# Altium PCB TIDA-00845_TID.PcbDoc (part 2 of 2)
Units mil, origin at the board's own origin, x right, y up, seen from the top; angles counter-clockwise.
Board outline 5936.8 x 4260 mil, 4 copper layers (Top Layer, Layer 2, Layer 3, Bottom Layer), stack 61.2 mil thick; 144 components, 62 nets, 439 pads, 261 vias.
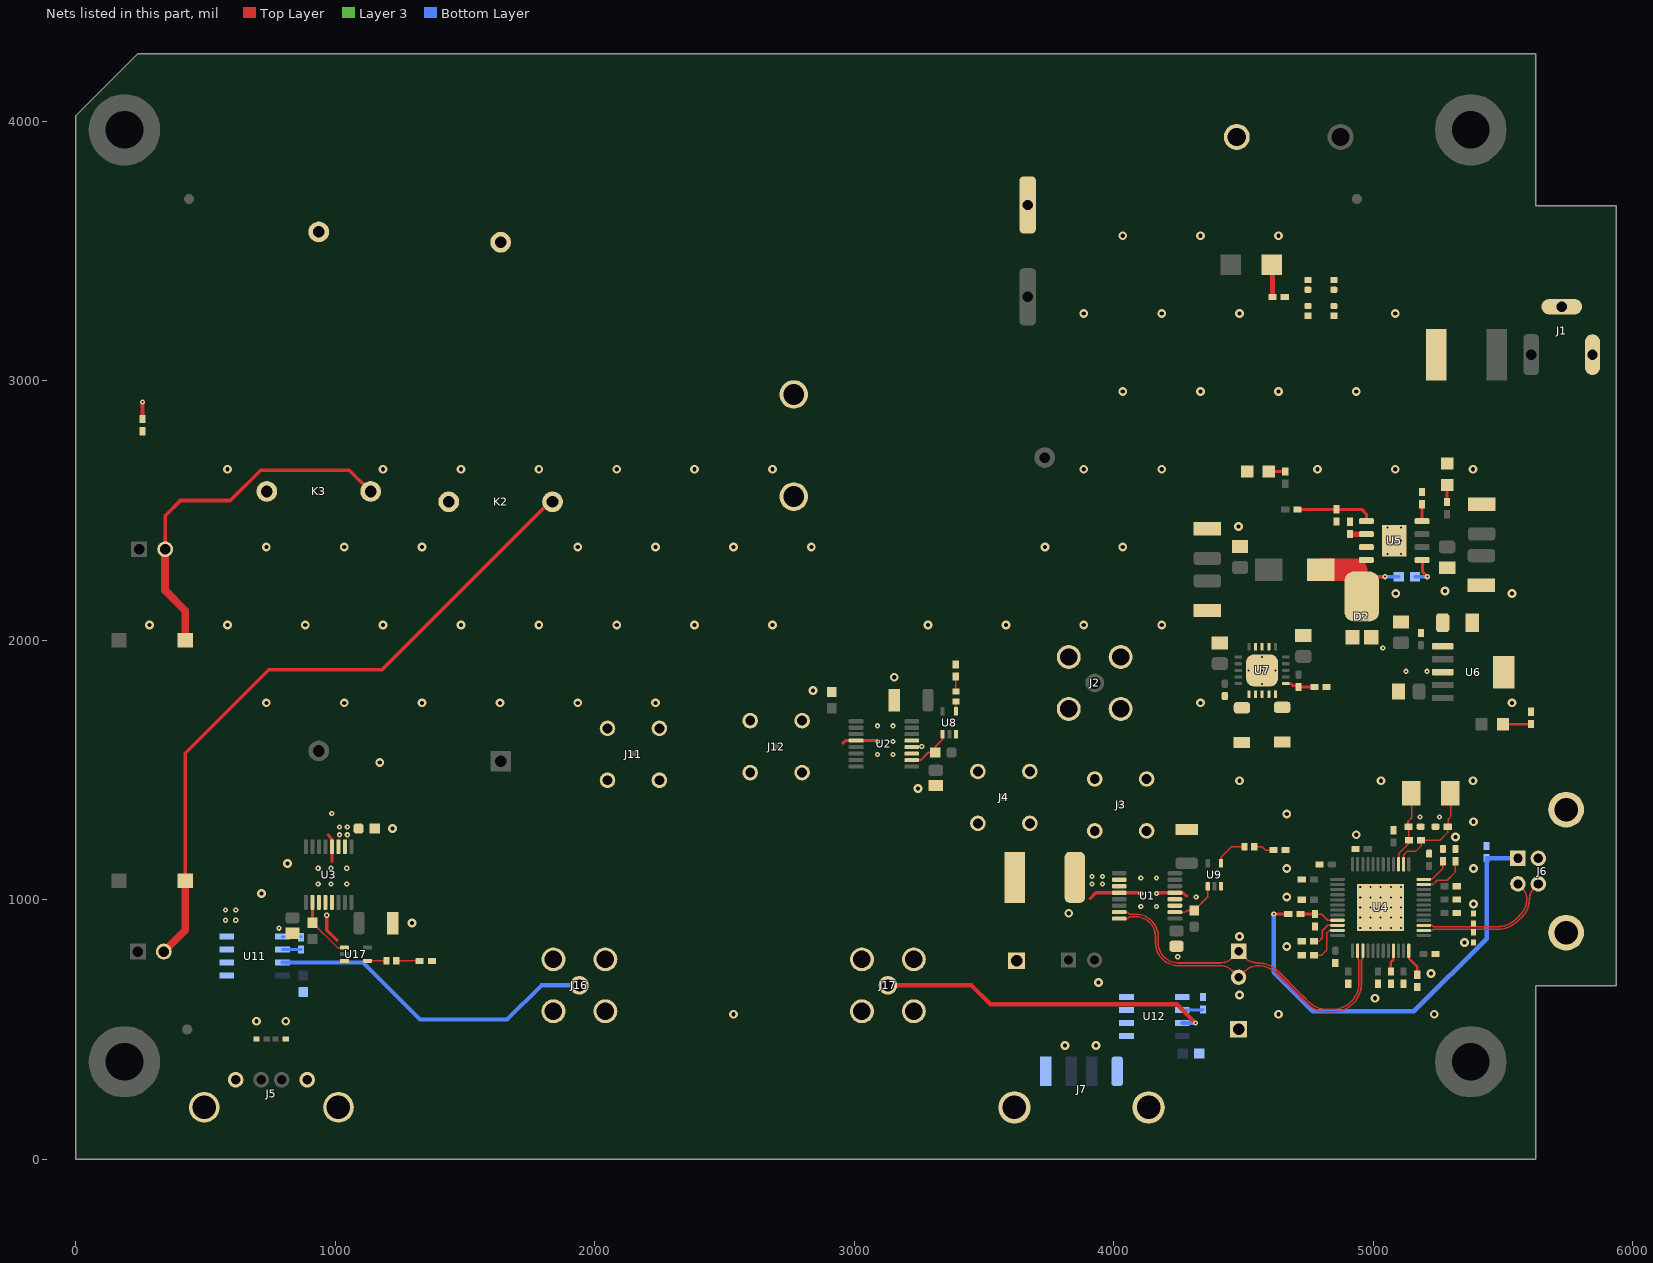
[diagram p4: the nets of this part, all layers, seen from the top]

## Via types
v1: diameter 19.68, hole 7.87, Top Layer to Bottom Layer, tented both sides, 170 vias
v2: diameter 34, hole 16, Top Layer to Bottom Layer, tented both sides, 91 vias

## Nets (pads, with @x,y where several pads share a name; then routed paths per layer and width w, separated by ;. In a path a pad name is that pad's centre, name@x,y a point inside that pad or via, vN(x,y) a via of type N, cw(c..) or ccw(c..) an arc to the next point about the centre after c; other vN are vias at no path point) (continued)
DP2_SYS_N: J8.2 U1.8 U4.15 | length 1344.2
  Top Layer w6.24: U1.8@4021.11,926.74 4053.03,926.74 4060.41,934.12 4083.95,934.12 cw(c4083.95,856.85) 4161.22,856.85 4161.18,833.32 ccw(c4248.69,833.32) 4248.69,745.81 4410.96,745.81 cw(c4410.96,684.19) 4454.53,727.76 J8.2@4481.36,700.93 4505.18,724.74 cw(c4556.03,673.89) 4556.03,745.81 cw(c4556.03,645.81) 4626.74,716.52 4709.96,633.3 4726.6,616.65 4743.25,600.01 ccw(c4821.2,677.96) 4821.2,567.72 4844.73,567.72 ccw(c4844.73,677.96) 4954.97,677.96 4954.97,767.83 4959.7,772.55 U4.15@4959.7,803.55 ccw(c4962.36,800.89) U4.15@4958.59,800.89
DP2_SYS_P: J8.1 U1.7 U4.14 | length 1328.1
  Top Layer w6.24: U1.7@4021.11,951.74 4053.03,951.74 4060.41,944.36 4083.95,944.36 cw(c4083.95,856.85) 4171.46,856.85 ; 4171.42,856.85 4171.42,833.32 ccw(c4248.69,833.32) 4248.69,756.05 4410.96,756.05 ccw(c4410.96,817.66) 4454.53,774.09 J8.1@4481.36,800.93 4505.18,777.11 ccw(c4556.03,827.96) 4556.03,756.05 cw(c4556.03,645.81) 4633.98,723.76 4717.2,640.54 4733.84,623.89 4750.49,607.25 ccw(c4821.2,677.96) 4821.2,577.96 4844.73,577.96 ccw(c4844.73,677.96) 4944.73,677.96 4944.73,767.83 4940.01,772.55 U4.14@4940.01,803.55 cw(c4937.35,800.89) U4.14@4941.11,800.89
FLT_U1: R26.1 U1.10 U9.1 | length 191.4
  Top Layer w6.24: U1.10@4235.68,951.74 4274.54,951.74 4281.29,958.5 R26.1@4309.8,958.5 4362.21,1010.91 U9.1@4362.21,1051.25
FLT_U2: R22.1 U2.10 U8.1 | length 185
  Top Layer w6: R22.1@3311.9,1567.05 3311.9,1589.46 3340.84,1618.4 U8.1@3340.84,1637.69
  Top Layer w8: U2.10@3221.68,1537.61 3255.84,1537.61 3285.28,1567.05 R22.1@3311.9,1567.05
FLT_U3: R23.2 U3.10 U17.1 | length 241.1
  Top Layer w6: R23.2@912.8,911.5 1008.7,815.59 U17.1@1035.84,815.59
  Top Layer w12: U3.10@912.31,989.64 912.31,911.98 R23.2@912.8,911.5
GND: C1.2 C3.2 C4.1 C5.1 C6.1 C7.2 C8.2 C9.2 C10.1 C11.2 C12.1 C13.2 C14.2 C15.1 C16.1 C17.2 C18.1 C19.1 C20.1 C21.1 C22.2 C23.1 C24.1 C25.1 C26.1 C27.1 C28.2 C29.2 C30.1 C31.1 C32.1 C33.1 C34.1 C35.1 C36.2 C37.2 C38.2 C39.2 C40.2 C41.2 C42.2 C43.2 C47.2 C48.2 C49.2 C50.2 C51.2 D1.2 D2.1 D2.2 D3.2 D10.2 D12.2 D13.2 D14.2 J1.2 J1.3 J2.2 J2.3 J2.4 J2.5 J3.2 J3.3 J3.4 J3.5 J4.2 J4.3 J4.4 J4.5 J5.4 J5.5 J5.6 J6.4 J6.5 J6.6 J7.4 J7.5 J7.6 J11.2 J11.3 J11.4 J11.5 J12.2 J12.3 J12.4 J12.5 J15.1 J16.2 J16.3 J16.4 J16.5 J17.2 J17.3 J17.4 J17.5 J18.1 K2.4 K3.4 R5.2 R6.2 R7.1 R15.1 R16.1 R17.2 R18.2 R19.1 R20.1 R21.1 R25.1 R27.2 R28.2 R31.2 U1.4 U1.11 U1.12 U1.13 U2.4 U2.11 U2.12 U2.13 U3.4 U3.11 U3.12 U3.13 U4.49 U5.7 U5.9 U6.3 U6.6 U7.2 U7.3 U7.4 U7.12 U7.13 U7.14 U7.21 U8.3 U9.3 U11.5 U12.5 U13.2 U14.2 U15.2 U16.2 U17.3 | length 2016.8
  Top Layer w10: 985.78,1235.66 U3.4@987.31,1204.21
  Top Layer w12: v1(967.63,940) 967.63,882.46 1007.39,842.69 ; 973.32,1248.82 984.87,1235.39 ; 987.31,1147.77 U3.4@987.31,1204.21 ; 2956.38,1602.65 2966.34,1612.61 U2.4@3007.11,1612.61 3087.62,1612.61 v1(3090.23,1610) ; 3909.03,1004.58 3931.2,1026.74 U1.4@4021.11,1026.74 4100.01,1026.74 v1@4101.43,1025.33 ; v1(4164.23,1024.13) 4166.84,1026.74 U1.13@4235.68,1026.74 4265.8,1026.74 4278.41,1014.13 4282.23,1014.13
  Layer 3 w18: v1(4949.85,891.15) v1(4949.85,930.52) v1(4949.85,969.89) v1(4949.85,1009.26) v1(4949.85,1048.63) v1(4989.22,1048.63) v1(5028.59,1048.63) v1(5067.96,1048.63) v1(5107.33,1048.63) v1(5107.33,1009.26) v1(5107.33,969.89) v1(5107.33,930.52) v1(5107.33,891.15) v1(5067.96,891.15) v1(5028.59,891.15) v1(4989.22,891.15) v1(4949.85,891.15)
  Bottom Layer w10: U11.5@796.92,857.89 C48.2@868.92,857.89
  Bottom Layer w18: v1(4949.85,891.15) v1(4949.85,930.52) v1(4949.85,969.89) v1(4949.85,1009.26) v1(4949.85,1048.63) v1(4989.22,1048.63) v1(5028.59,1048.63) v1(5067.96,1048.63) v1(5107.33,1048.63) v1(5107.33,1009.26) v1(5107.33,969.89) v1(5107.33,930.52) v1(5107.33,891.15) v1(5067.96,891.15) v1(5028.59,891.15) v1(4989.22,891.15) v1(4949.85,891.15)
  other v1: 4246.8,780 782.99,890 4989.22,930.52 5028.59,930.52 5067.96,930.52 4989.22,969.89 5028.59,969.89 5067.96,969.89 4104.23,974.13 4164.23,974.13 4989.22,1009.26 5028.59,1009.26 5067.96,1009.26 4317.8,1010 4104.23,1024.13 934.7,1061.09 984.7,1061.09 1044.7,1061.09 4104.23,1084.13 4164.23,1084.13 934.7,1121.09 984.7,1121.09 1044.7,1121.09 5179.89,1318.96 5255.7,1318.87 987.04,1332.23 3090.23,1560 3150.23,1560 3260.23,1590 3150.23,1610 3090.23,1670 3150.23,1670 4571.96,1831.22 5126.8,1880 5206.8,1880 4519.79,1883.39 4571.96,1883.39 4624.12,1883.39 4571.96,1935.55 5036.8,1970 5055.2,2332.31 5106.38,2332.31 5055.2,2383.49 5106.38,2383.49 5055.2,2434.67 5106.38,2434.67
  other v2: 3812.54,438.59 3931.6,438.1 697.11,531.49 809.48,531.49 2534.8,558.5 4634.8,558.5 5234.8,558.5 5006.8,620 4484.8,633.3 3941.34,680.4 5222.96,716.16 4666.8,820 5351.58,835.24 4484.8,858.5 1296.25,910.36 3826.8,947.81 5386.8,983 4666.8,1010 715.69,1024.13 4666.8,1120 5386.8,1120 815.8,1139.84 5317.4,1240.96 4934.8,1250 1221.56,1273.76 5386.8,1300 4666.8,1330 3246.29,1428.36 4484.8,1458.5 5030.11,1458.5 5384.8,1458.5 1171.86,1528.07 734.8,1758.5 1034.8,1758.5 1334.8,1758.5 1634.8,1758.5 1934.8,1758.5 2234.8,1758.5 4334.8,1758.5 5534.8,1758.5 2841.52,1806.12 3154.07,1857.2 284.8,2058.5 584.8,2058.5 884.8,2058.5 1184.8,2058.5 1484.8,2058.5 1784.8,2058.5 2084.8,2058.5 2384.8,2058.5 2684.8,2058.5 3284.8,2058.5 3584.8,2058.5 3884.8,2058.5 4184.8,2058.5 5086.8,2180 5534.8,2180 5276.8,2190 734.8,2358.5 1034.8,2358.5 1334.8,2358.5 1934.8,2358.5 2234.8,2358.5 2534.8,2358.5 2834.8,2358.5 3734.8,2358.5 4034.8,2358.5 4480.42,2438.54 584.8,2658.5 1184.8,2658.5 1484.8,2658.5 1784.8,2658.5 2084.8,2658.5 2384.8,2658.5 2684.8,2658.5 3884.8,2658.5 4184.8,2658.5 4784.8,2658.5 5084.8,2658.5 5384.8,2658.5 4034.8,2958.5 4334.8,2958.5 4634.8,2958.5 4934.8,2958.5 3884.8,3258.5 4184.8,3258.5 4484.8,3258.5 5084.8,3258.27 4034.8,3558.5 4334.8,3558.5 4634.8,3558.5
NetC1_1: C1.1 K2.1 K3.1 R4.2 R7.2 S1.1 | length 65.4
  Top Layer w15: R7.2@257.6,2852.36 v1(257.6,2917.74)
NetC2_1: C2.1 D2.3 L1.1 U5.8 | length 230.8
  Top Layer w12: D2.3@5004.8,2244.49 v1(5045.8,2244.49)
  Top Layer w86.61: L1.1@4798.19,2271 4933.05,2271 4934.8,2269.25
  Bottom Layer w12: v1(5045.8,2244.49) C2.1@5098.3,2244.49
NetC2_2: C2.2 U5.1 | length 119.3
  Top Layer w12: U5.1@5188.07,2308.49 5189.78,2306.78 5189.78,2262.92 v1(5208.21,2244.49)
  Bottom Layer w12: C2.2@5161.29,2244.49 v1(5208.21,2244.49)
NetC10_2: C10.2 U5.6 | length 63.9
  Top Layer w12: C10.2@4909.79,2408.87 C10.2@4910.17,2408.49
  Top Layer w22: C10.2@4910.17,2408.49 U5.6@4973.5,2408.49
NetC12_2: C12.2 U4.11 | length 167.6
  Top Layer w6: C12.2@4771.79,786.03 4800.47,786.03 4821.6,807.17 4821.6,871.5 4831.42,881.31 U4.11@4862.26,881.31
NetC13_1: C13.1 R8.1 U4.39 Y1.1 | length 297.5
  Top Layer w6: U4.39@5097.49,1136.23 5097.49,1176.55 5137.19,1216.25 R8.1@5137.19,1229.21 5137.19,1279.33 C13.1@5135.37,1281.15 5133.99,1282.53 5133.99,1301.65 5148.41,1316.07 Y1.1@5148.41,1410
NetC14_1: C14.1 R8.2 U4.38 Y1.2 | length 411.2
  Top Layer w6: U4.38@5117.18,1136.23 5117.18,1172.11 5132.26,1187.19 5164.55,1187.19 5184.43,1207.07 R8.2@5184.43,1229.21 5256.92,1229.21 5288.36,1260.65 5286.98,1262.03 C14.1@5286.98,1281.15 5289.28,1283.45 5289.28,1310.22 5298.02,1318.96 Y1.2@5298.02,1410
NetC15_2: C15.2 R13.1 U6.1
NetC16_2: C16.2 R14.1 U7.11
NetC18_2: C18.2 U7.15
NetC48_1: C48.1 U11.6 | length 72.1
  Bottom Layer w10: U11.6@796.96,807.85 C48.1@868.96,807.85
NetC50_1: C50.1 U12.6 | length 80.3
  Bottom Layer w12: U12.6@4264.08,575 4341.09,575 C50.1@4343.39,577.3
NetC51_1: C51.1 J6.1 R24.1 | length 1709.6
  Top Layer w12: v1(4616.8,944.3) R24.1@4672.55,944.3
  Bottom Layer w18: v1(4616.8,944.3) 4616.8,720 4766.8,570 5156.8,570 5436.8,850 C51.1@5436.8,1160.13 5437.82,1159.11 J6.1@5557.64,1159.11
NetD1_1: D1.1 R1.1 | length 65
  Top Layer w12: R1.1@5284.8,2532.62 D1.1@5284.8,2597.66
NetD3_1: D3.1 R3.2 | length 64
  Top Layer w12: D3.1@4597.17,2649.64 R3.2@4661.17,2649.64
NetD7_2: D7.2 R15.2 | length 108.2
  Top Layer w10: D7.2@5499.79,1675.86 5606.38,1675.86 R15.2@5607.51,1677
NetD8_1: D8.1 U8.4 | length 35.2
  Top Layer w6: U8.4@3392.02,1726.27 D8.1@3392.02,1761.46
NetD8_2: D8.2 R27.1 | length 60.8
  Top Layer w6: R27.1@3391.45,1859.37 3392.02,1858.8 D8.2@3392.02,1798.86
NetD9_1: D9.1 U9.4 | length 131.5
  Top Layer w6: U9.4@4413.39,1139.84 4413.39,1163.59 4454.01,1204.21 D9.1@4504.31,1204.21
NetD9_2: D9.2 R28.1 | length 78.9
  Top Layer w6: D9.2@4541.71,1204.21 4570.59,1204.21 4583.8,1191 R28.1@4615.17,1191
NetD10_1: D10.1 D12.1 D13.1 D14.1 R30.2
NetD11_2: D11.2 R30.1 | length 125.8
  Top Layer w20: D11.2@4608.35,3447.15 4611.96,3443.54 R30.1@4611.96,3322.83
NetD15_1: D15.1 U17.4 | length 73.7
  Top Layer w6: U17.4@1124.42,764.41 D15.1@1198.1,764.41
NetD15_2: D15.2 R31.1 | length 90
  Top Layer w6: D15.2@1235.5,764.41 R31.1@1325.49,764.41
NetJ13_2: J13.2 K2.3 S2.1 | length 2619.3
  Top Layer w14: S2.1@422.75,1073 422.75,1564.75 743.8,1885.8 1180.49,1885.8 K2.3@1837.8,2543.11
  Top Layer w30: J13.2@340,800 422.75,882.75 S2.1@422.75,1073
NetJ14_2: J14.2 K3.3 S3.1 | length 1420.2
  Top Layer w14: J14.2@344.8,2350 344.8,2479.01 403.87,2538.08 596.07,2538.08 713.19,2655.2 1054.6,2655.2 K3.3@1143.8,2566
  Top Layer w30: J14.2@344.8,2350 344.8,2191.4 422.75,2113.44 S3.1@422.75,2000
NetJ16_1: J16.1 U11.7 | length 1289.7
  Bottom Layer w16: U11.7@796.92,757.89 1107.12,757.89 1326.8,538.21 1662.9,538.21 1794.69,670 J16.1@1941.05,670
NetJ17_1: J17.1 U12.7 | length 1296.9
  Top Layer w16: J17.1@3129.74,670 3452.58,670 3525.55,597.03 4243.3,597.03 v1(4315.33,525)
  Bottom Layer w16: U12.7@4264.08,525 v1(4315.33,525)
NetR2_2: R2.2 R5.1 U5.5 | length 300.3
  Top Layer w12: R2.2@4708.42,2504.11 R5.1@4858.79,2504.11 4955.69,2504.11 4973.5,2486.29 U5.5@4973.5,2458.49
NetR6_1: R6.1 U5.4 | length 64.9
  Top Layer w12: U5.4@5188.07,2458.49 R6.1@5188.07,2523.38
NetR12_1: R12.1 R16.2 U7.16 | length 114.8
  Top Layer w10.5: U7.16@4663.49,1832.2 4683.21,1832.2 4691.46,1823.96 4707.76,1823.96 R12.1@4711.96,1819.76 R16.2@4773.12,1819.76
NetR17_1: R17.1 U4.24 | length 106.3
  Top Layer w10: U4.24@5136.86,803.55 5136.86,773.93 5169.79,741 R17.1@5169.8,710.94
NetR18_1: R18.1 U4.10 | length 131.4
  Top Layer w6: R18.1@4771.79,839.89 4790.56,839.89 4803.91,853.24 4803.91,879.92 4824.98,901 U4.10@4862.26,901
NetR19_2: R19.2 U4.21 | length 84.1
  Top Layer w10: R19.2@5067.96,723.51 5067.96,759.55 5077.81,769.39 U4.21@5077.81,803.55
NetR20_2: R20.2 U4.35 | length 183.3
  Top Layer w6: U4.35@5194.93,1058.48 5229.84,1058.48 5246.26,1074.9 5284.77,1074.9 5316.59,1106.73 R20.2@5316.59,1148.33
NetR21_2: R21.2 U4.36 | length 118.4
  Top Layer w6: U4.36@5194.93,1078.16 5225.22,1078.16 5268.59,1121.54 R21.2@5268.59,1148.33
NetR24_2: R24.2 R25.2 U4.9 | length 152.2
  Top Layer w6: R25.2@4776.17,944.3 4801.32,944.3 4824.94,920.68 U4.9@4862.26,920.68
  Top Layer w12: R24.2@4719.79,944.3 R25.2@4776.17,944.3
UP_N: J6.2 U4.27 U15.1 | length 525.6
  Top Layer w6.24: U4.27@5194.93,901 5225.93,901 5230.66,896.27 ; 5230.66,896.29 5479.77,896.29 ccw(c5479.77,996.29) 5550.48,925.58 5566.5,941.59 ccw(c5505.2,1002.89) 5591.89,1002.89 ccw(c5535.06,1002.89) 5575.24,1043.07 J6.2@5557.64,1060.68
UP_P: J6.3 U4.26 U16.1 | length 541.7
  Top Layer w6.24: U4.26@5194.93,881.31 5225.93,881.31 5230.66,886.03 5479.77,886.05 ccw(c5479.77,996.29) 5557.72,918.34 5573.74,934.35 ccw(c5505.2,1002.89) 5602.13,1002.89 cw(c5658.95,1002.89) 5618.77,1043.07 J6.3@5636.38,1060.68
VBUS1_CON_SENSE_IN: C28.1 U3.2 U3.3 U11.3 U11.4
  other v1: 577.03,920.65 617.03,920.65 577.03,960.65 617.03,960.65 1016.8,1250 1046.8,1250 1016.8,1280 1046.8,1280
VBUS1_CON_SENSE_OUT: J5.1 U11.1 U11.2
VBUS2_CON_SENSE_IN: C36.1 U1.2 U1.3 U12.3 U12.4
  other v1: 3916.8,1060 3956.8,1060 3916.8,1090 3956.8,1090
VBUS2_CON_SENSE_OUT: J7.1 U12.1 U12.2
pads on no net: FID1.1 FID2.1 FID3.1 H1.1 H2.1 H3.1 H4.1 U1.1 U1.16 U2.1 U2.16 U3.1 U3.16 U4.2 U4.3 U4.4 U4.5 U4.6 U4.8 U4.16 U4.17 U4.19 U4.20 U4.22 U4.28 U4.29 U4.31 U4.32 U4.43 U4.44 U4.46 U4.47 U7.9 U7.17

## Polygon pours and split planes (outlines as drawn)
DP1_STB_VBUS on Top Layer "Top_Power" (solid, remove dead copper, pour order 312): 2994.8,1629.86 3033.8,1629.86 3035.8,1631.86 3035.8,1632.86 3035.8,1666.86 3031.8,1670.86 3028.8,1670.86 2967.8,1670.86 2945.8,1692.86 2945.8,1745.86 2881.8,1745.86 2881.8,1629.86
+3P3 on Top Layer "Top_Power" (solid, pour order 306): 3193.23,1519.99 3193.23,1500 3216.23,1477 3245.23,1477 3422.07,1477 3422.07,1585 3355.23,1585 3290.23,1520
+5V on Top Layer "Top_Power_1a" (solid, pour order 269): 3263.13,1747.42 3263.13,1686.22 3247.77,1670.86 3239.8,1670.86 3192.8,1670.86 3192.8,1629.86 3305.21,1629.86 3305.21,1737.69
+3P3 on Top Layer "Top_Power_1a" (solid, pour order 267): 5218.79,856.89 5214.79,852.89 5214.79,780 5174.79,780 5174.79,852.89 5171.79,855.89 5171.79,856.89
+3P3 on Top Layer "Top_Power_1a" (solid, pour order 268): 5141.59,1160.09 5145.59,1156.09 5226.8,1156.09 5226.8,1116.09 5145.59,1116.09 5142.59,1113.09 5141.59,1113.09
+3P3 on Top Layer "Top_Power_1a" (solid, pour order 271): 4920.51,1107.45 4911.59,1116.37 4824.47,1116.37 4824.47,1156.37 4911.59,1156.37 4914.59,1159.37 4920.51,1159.37
+1P1 on Top Layer "Top_Power_1a" (solid, pour order 270): 4839.79,856.89 4839.79,787.89 4881.79,787.89 4881.79,852.89 4885.79,856.89 4885.79,857.89 4884.79,856.89 4839.79,856.89
NetC2_1 on Top Layer "Top_Power_1b" (solid, pour order 282): 4843.47,2320 5001.8,2320 5001.8,2291 5021.8,2271 5021.8,2268 5021.8,2072 5020.8,2073 4879.8,2073 4843.47,2109.33
+5V on Top Layer "Top_Power" (solid, pour order 293): 4650.8,2314.86 4307.55,2314.86 4307.55,2228 4650.8,2228
+18V on Top Layer "Top18V" (solid, remove dead copper, pour order 285): 5158.8,2421 5237.8,2421 5253.8,2437 5297.39,2437 5475.11,2437 5499.75,2461.64 5499.83,3203.75 5579.71,3203.75 5637.16,3203.75 5684.58,3156.32 5684.58,2392.42 5590.16,2298 5505.8,2298 5487.8,2298 5357.8,2298 5322.8,2333 5236.77,2333 5224.77,2345 5219.8,2345 5158.8,2345
+5V on Top Layer "Top_Power" (solid, remove dead copper, pour order 294): 4525.96,1989.46 4494.96,1989.46 4439.96,1989.46 4440.07,1934.57 4377.96,1934.57 4377.97,1883.39 4413.29,1848.06 4413.96,1846.46 4413.96,1815.46 4414.96,1814.46 4495.09,1814.46 4494.96,1837.46 4459.96,1837.46 4439.96,1857.46 4439.96,1862.46 4440.96,1863.46 4440.96,1877.46 4494.96,1877.46 4494.96,1944.46 4509.96,1959.46 4510.96,1960.46 4525.96,1960.46
NetC16_2 on Top Layer "Top_Power" (solid, remove dead copper, pour order 295): 4526.58,1806.46 4415.96,1806.46 4415.96,1764.46 4462.96,1717.46 4464.67,1717.46 4526.58,1717.46 4526.58,1806.46
NetC18_2 on Top Layer "Top_Power" (solid, pour order 296): 4616.96,1806.46 4616.96,1719.46 4680.96,1719.46 4680.96,1764.46 4638.96,1806.46 4632.96,1806.46 4616.96,1806.46
+1P1 on Top Layer "Top_Power" (solid, remove dead copper, pour order 297): 4648.96,1877.46 4678.96,1877.46 4678.96,1851.46 4777.96,1851.46 4777.96,1895.46 4788.51,1906.01 4896.8,1906.71 4896.8,1961.46 4698.96,1961.46 4678.96,1941.46 4674.96,1941.46 4648.96,1941.46 4647.96,1940.46 4647.96,1877.46
+3P3 on Top Layer "Top_Power" (solid, pour order 298): 5308.8,1838 5150.8,1838 5150.8,1690 5308.8,1690
NetC15_2 on Top Layer "Top_Power" (solid, pour order 299): 5293.8,2104 5293.8,2022 5308.8,2007 5308.8,1996 5308.8,1959 5174.8,1959 5174.8,2055 5223.8,2104 5293.8,2104
+5V on Top Layer "Top_Power" (solid, pour order 300): 4416.8,1815 4333.8,1815 4333.8,1934.57 4416.8,1934.57
+5V on Top Layer "Top_Power" (solid, pour order 304): 4288.25,1160.49 4276.77,1137 4276.77,1100 4261.77,1085 4253.8,1085 4206.8,1085 4206.8,1044 4323.27,1044 4323.27,1153.92 4290.42,1161.52
+3P3 on Top Layer "Top_Power" (solid, pour order 308): 4213.8,934 4328.8,934 4328.8,858 4213.8,858
+3P3 on Top Layer "Top_Power" (solid, remove dead copper, pour order 318): 4364.09,892.55 4364.09,822 4282.1,822 4282.1,892.55
GND on Top Layer "Top_DGND" (solid, remove dead copper, pour order 332): 0,4260 5626.8,4260 5626.8,3673.5 5936.8,3673.5 5936.8,668.5 5626.8,668.5 5626.8,0 0,0
+5V on Top Layer "Top_Power1" (solid, pour order 292): 5222.8,1917 5074.8,1917 5074.8,1996 5195.8,1996 5195.8,1964 5222.8,1937 5222.8,1918
VBUS2_CON_SENSE_IN on Top Layer "Top_Power" (solid, remove dead copper, pour order 310): 4008.8,1044 4047.8,1044 4049.8,1046 4049.8,1047 4049.8,1081 4045.8,1085 4042.8,1085 3981.8,1085 3891.9,1174.9 3840.89,1174.9 3840.89,1087.57 3840.89,1056.29 3853.19,1044
VBUS1_CON_SENSE_IN on Top Layer "Top_Power" (solid, remove dead copper, pour order 314): 1003.8,1185 1003.8,1181 1009.8,1175 1010.8,1175 1038.8,1175 1040.8,1175 1045.8,1180 1045.8,1186 1045.8,1223 1045.8,1231.15 1070.19,1255.55 1084.7,1255.55 1084.7,1292.97 1003.8,1292.97
+5V on Top Layer "Top_Power" (solid, remove dead copper, pour order 301): 1004.8,1012 1004.8,1015 1007.8,1018 1009.8,1018 1040.8,1018 1044.8,1014 1044.8,965 1056.8,953 1065.8,953 1112.8,953 1112.8,867 1004.8,867 1004.8,1012
+5V on Top Layer "Top_5V" (solid, remove dead copper, pour order 302): 46.69,781.97 46.69,2331.74 74.93,2359.99 116.6,2360.02 116.86,785.55 81.73,750.41 78.25,750.41
+3P3 on Top Layer "Top_Power" (solid, remove dead copper, pour order 313): 892.33,1012.31 863.95,1012.15 815.8,964 815.8,909 862.8,909 864.58,910.78 864.58,951.26 877.32,964 879.8,964 892.8,964 892.33,964.46
+5V on Top Layer "Top_Power" (solid, pour order 305): 4434.95,2313.8 4434.95,2058.27 4534.96,2058.27 4534.96,2313.8
NetD10_1 on Top Layer "Top_D10" (solid, remove dead copper, pour order 278): 4860.97,3360 4695.66,3360 4658.49,3322.83 4701.14,3280.19 4860.97,3278.24
+1P1 on Top Layer "L1_1pt1" (solid, remove dead copper, pour order 65): 4617.14,1989.39 4673.33,1989.39 4704.19,1958.53 4704.19,1956.39 4704.19,1940 4648.19,1940 4617.14,1971.04 4617.14,1989.39
+5V on Top Layer "Top Layer-5Vg" (solid, remove dead copper, pour order 59): 100,1430 140,1430 160,1410 160,1360 140,1340 100,1340
GND on Layer 2 "L2_DGND" (solid, remove dead copper, pour order 330): 0,4260 5626.8,4260 5626.8,3673.5 5936.8,3673.5 5936.8,668.5 5626.8,668.5 5626.8,0 0,0
NetC1_1 on Layer 2 "L2_Cap_18V" (solid, remove dead copper, pour order 322): 0,4260 3791.03,4260 3791.03,3414.64 3217.64,2841.26 0,2841.26
NetC1_1 on Layer 2 "L2_Cap_18" (solid, remove dead copper, pour order 277): 3790.22,4260 3790.22,3518.74 3314.58,3518.74 3314.58,4260
VBUS1_CON_SENSE_OUT on Bottom Layer "Bot_5Vb" (solid, pour order 281): 553.87,620.5 553.87,770.65 609.84,770.65 638.83,741.67 638.83,620.5
VBUS1_CON_SENSE_IN on Bottom Layer "Bot_VBUS1_SYS" (solid, pour order 316): 553.87,976.72 553.87,795.3 608.65,795.3 638.83,825.47 638.83,976.72
VBUS1_CON_SENSE_OUT on Bottom Layer "Bot_5Va" (solid, pour order 283): 786.26,420 786.26,388.31 858.16,316.4 869.8,316.4 869.8,420
VBUS1_CON_SENSE_OUT on Bottom Layer "Bot_5Vaaa" (solid, pour order 280): 936.28,357.18 936.28,287.84 921.68,273.24 863.3,273.24 851.32,285.22 851.32,419.41 874.05,419.41
VBUS1_CON_SENSE_OUT on Bottom Layer "Bot_5Va" (solid, pour order 284): 580.81,684.4 608.93,684.4 915.35,377.97 796.68,377.97 554.28,620.36
VBUS2_CON_SENSE_IN on Bottom Layer "Bot_5V_1" (solid, remove dead copper, pour order 287): 3896.8,1100 3906.8,1110 3966.8,1110 4134.81,941.99 4134.81,617.4 4078.17,560.77 4021.36,560.77 4021.36,915.43 3896.8,1040
GND on Bottom Layer "Bot_DGND" (solid, remove dead copper, pour order 329): 0,4260 5626.8,4260 5626.8,3673.5 5936.8,3673.5 5936.8,668.5 5626.8,668.5 5626.8,0 0,0
+3P3 on Bottom Layer "Bot_3p3" (solid, remove dead copper, pour order 317): 5169.63,1770 5246.8,1770 5264.55,1752.25 5266.8,1750 5266.8,830 5126.8,690 4736.8,690 4736.8,800 4736.8,1100 5146.8,1510 5146.8,1620 5146.8,1747.17
VBUS2_CON_SENSE_OUT on Bottom Layer "Bot_5V" (solid, remove dead copper, pour order 303): 4079.83,537.43 4021.59,537.43 3991.89,507.73 3991.89,281.25 4079.84,281.25
GND on Bottom Layer "Bot_AGND_Priority" (solid, remove dead copper, pour order 291): 4989.22,930.52 4986.8,928.1 4986.8,850 4936.8,800 4936.8,650 5156.8,650 5231.8,725 5146.8,810 5146.8,860 5147.75,860.96 5147.75,960.05 5137.91,969.89 4989.22,969.89
DP1_STB_VBUS on Layer 3 "L3_STB" (solid, remove dead copper, pour order 286): 2961.8,2030.12 2881.8,2030.12 2881.8,1640 2891.8,1630 2951.8,1630 2961.8,1640 2961.8,2000
+3P3 on Layer 3 "L3_3p3_2" (solid, remove dead copper, pour order 288): 863.95,1012.15 815.8,964 815.8,790 1004.87,600.93 1495.13,600.93 1721.19,826.99 4227.97,826.99 4370.06,684.9 4793.17,684.9 4809.67,701.39 4809.67,704.3 4809.67,750 4795.29,764.38 4652.19,764.38 4516.8,764.71 3733.15,1548.35 3572.71,1548.35 3348.07,1548.35 3080.86,1281.15 1720.15,1281.15 1265.99,826.99 1254.83,826.99 946.8,826.99 882.33,891.45 882.33,995.89 868.22,1010 864.58,1010
+5V on Layer 3 "L3_5V" (solid, remove dead copper, pour order 290): 83.22,1353.68 83.22,1415.89 97.32,1430 1566.8,1430 1566.8,951.26 1066.8,951.26 1105.54,990 1106.8,990 1101.76,995.04 1101.76,1302.77 1064.53,1340 96.9,1340
+18V on Layer 3 "L3_18V" (solid, remove dead copper, pour order 320): 4690.28,3830 4699.97,3830 5573.04,2956.92 5936.8,2956.92 5936.8,3673.5 5626.8,3673.5 5626.8,4260 4690.28,4260
+1P1 on Layer 3 "L3_1p1" (solid, remove dead copper, pour order 307): 4825.42,1978.01 4865.42,1978.01 4885.42,1958.01 4885.42,1938.01 4885.42,1348.01 5196.8,1036.63 5196.8,990 5126.8,920 4986.8,920 4880.57,818.01 4815.42,818.01 4785.42,848.01 4765.42,868.01 4765.42,1958.01 4785.42,1978.01
+5V on Layer 3 "L3_5V" (solid, remove dead copper, pour order 311): 4446.75,2218.38 4526.84,2218.38 4536.8,2208.43 4536.8,2140 4566.8,2110 4586.8,2090 5106.8,2090 5206.8,1990 5206.8,1980 5206.8,1930 5196.8,1920 5186.8,1920 4716.8,1920 4656.8,1980 4526.8,1980 4466.8,1920 4456.8,1920 4466.8,1920 4406.8,1860 4406.8,1840 4406.8,1820 4396.8,1810 4336.8,1810 4326.8,1820 4326.8,1920 4436.8,2030 4436.8,2208.43
+5V on Layer 3 "L3_5V" (solid, remove dead copper, pour order 309): 4326.8,1920 4216.8,1920 4013.32,1716.53 4013.32,1293.47 4256.8,1050 4266.8,1040 4316.8,1040 4326.8,1050 4326.8,1550 4246.8,1550 4246.8,1820 4326.8,1820
+5V on Layer 3 "L3_5V_3" (solid, pour order 289): 4176.8,1278.38 3858.43,1278.38 3406.96,826.91 1048.96,826.91 996.8,879.07 996.8,947 1414.23,1364.43 2634.79,1870 4176.8,1870
NetC1_1 on Layer 3 "L3_18V_Cap" (solid, remove dead copper, pour order 272): 0,4260 3601.32,4260 3601.32,3224.33 3217.64,2840.65 0,2840.66
VBUS1_CON_SENSE_IN on Layer 3 "L3_5V" (solid, remove dead copper, pour order 315): 1066.8,1290 1050.64,1306.16 712.95,1306.15 553.73,1146.93 553.73,917.72 569.04,902.4 621.47,902.4 638.69,919.62 638.69,1102.02 762.53,1225.86 1052.65,1225.86 1066.8,1240
GND on Layer 3 "L3_DGND" (solid, remove dead copper, pour order 331): 0,4260 5626.8,4260 5626.8,3673.5 5936.8,3673.5 5936.8,668.5 5626.8,668.5 5626.8,0 0,0
+1P1 on Layer 3 "L3_1p1" (solid, remove dead copper, pour order 319): 4828.79,818.01 4936.8,710 4956.8,710 5006.8,710 5016.8,720 5016.8,750 5016.8,830 5016.8,870 5016.8,880 5016.8,890 4986.8,920 4964.63,942.16 4960.94,942.16 4961.41,942.63 4961.41,945.92 4957.33,950 4946.8,950 4826.8,830 4826.8,820 4828.79,818.01
NetC1_1 on Layer 3 "L3_+18V1" (solid, remove dead copper, pour order 276): 4691.69,4260 4691.69,3467.1 3305.92,3467.1 3305.92,4260
DP1_STB_VBUS on Layer 3 "L3_STB_a" (solid, remove dead copper, pour order 279): 3781.13,3541.1 3781.13,2689.01 2950.92,1858.8 2885.25,1858.8 2885.25,2674.78 2890.81,2680.34 3291.06,3080.92 3291.06,3089.1 3743.06,3541.1

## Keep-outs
Keep-Out Layer:
  lines w10: -5,4027.07 -5,-5 5631.8,-5 5631.8,663.5 5941.8,663.5 5941.8,3678.5 5631.8,3678.5 5631.8,4265 232.93,4265 -5,4027.07 ; -5,4027.07 -5,4027.07
  text ".Layer_Name" at 203.8,-1315.99 h60

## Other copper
Top Layer:
  pour cut-out: 4552.13,2416.67 4843.47,2416.67 4843.47,2125.33 4552.13,2125.33
  pour cut-out: 4090.74,1544.19 4090.74,2855 5429.75,2855 5500.38,2855 5500.38,2799.18 4164.23,2799.18 4161.88,2796.84 4161.88,1544.19
  pour cut-out: 5067.96,1489.75 5363.64,1489.75 5363.64,1336.07 5067.96,1336.08
  text ".Layer_Name" at 203.8,-1315.99 h60
Layer 2:
  pour cut-out: 4550.46,2416.67 4841.8,2416.67 4841.8,2125.33 4550.46,2125.33
  pour cut-out: 4090.74,1543.11 4090.74,2855 5429.75,2855 5500.38,2855 5500.38,2799.18 4164.23,2799.18 4161.88,2796.84 4161.88,1543.11
Layer 3:
  pour cut-out: 4550.46,2416.67 4841.8,2416.67 4841.8,2125.33 4550.46,2125.33
  pour cut-out: 4092.5,1894.41 cw(c4092.5,1896.16) 4090.74,1896.16 4090.74,2855 5427.79,2855 5500.37,2855 5500.37,2799.18 4164.23,2799.18 4161.88,2796.84 4161.88,1893.93 4161.4,1894.41
Bottom Layer:
  pour cut-out: 4552.13,2416.67 4843.47,2416.67 4843.47,2125.33 4552.13,2125.33
  pour cut-out: 4090.74,1870 4090.74,2855 5429.75,2855 5500.38,2855 5500.38,2799.18 4164.23,2799.18 4161.88,2796.84 4161.88,1870
  text ".Layer_Name" at 203.8,-1315.99 h60

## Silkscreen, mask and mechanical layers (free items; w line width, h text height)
Top Overlay:
  lines w5: 3282.73,1410 3345.72,1410 ; 3282.73,1527 3345.72,1527 ; 4217.8,792 4267.17,792 ; 4217.8,908 4267.17,908
  lines w6: 5191.8,1462 5251.8,1462 ; 5192.8,1360 5252.8,1360
  lines w10: 4363.51,3840.16 4983.51,3840.16 4983.51,4040.16 4363.51,4040.16 4363.51,3840.16
  text ".Prj_Number" at 1162.21,3896.42 h125
  text "STB" at 4934.8,3417.32 h150
  text "+18V" at 5121.22,2773.65 h90
  text "+5V" at 4440.96,2770 h90
  text "CON" at 3591.58,2509.04 h90
  text "VBUS" at 3546.45,2256 h125
  text "SYS" at 3812.47,2024.5 h90
  text "D+" at 210,1820 h75
  text "FLT" at 3436.49,1720.64 h90
  text "CON" at 2295.91,1708.82 h90
  text "SYS" at 3764.32,1531.02 h60
  text "D+" at 3555.22,1528.64 h90
  text "+3.3V" at 5353.8,1525 h90
  text "D-" at 3980.26,1520.23 h90
  text "D+" at 2651.65,1339.34 h90
  text "D-" at 2093.93,1313.52 h90
  text "FLT" at 4486.51,1247.14 h90
  text "D-" at 490.32,1025.54 h75
  text "I" at 1664.64,956.74 h110
  text "I" at 2846.27,954.55 h110
  text "VBUS_1" at 1732.95,879.14 h90
  text "VBUS_2" at 2914.59,876.95 h90
  text "FLT" at 1130.78,597.33 h90
  text ".Layer_Name" at 203.8,-1315.99 h60
Bottom Overlay:
  text ".Layer_Name" at 203.8,-1315.99 h60
Top Paste:
  text ".Layer_Name" at 203.8,-1315.99 h60
Bottom Paste:
  text ".Layer_Name" at 203.8,-1315.99 h60
Top Solder:
  text ".Layer_Name" at 203.8,-1315.99 h60
  text ".Layer_Name" at 203.8,-1315.99 h60
Bottom Solder:
  text ".Layer_Name" at 203.8,-1315.99 h60
Drill Guide:
  text ".Layer_Name" at 203.8,-1315.99 h60
M1 Board Outline:
  the board outline again, w10
  text ".Layer_Name" at 203.8,-1315.99 h60
M2 Board Dimensions:
  rectangle: -248.2,-857.5 126.8,-732.5
  rectangle: -373.2,-732.5 -248.2,-607.5
  lines w7: -373.2,-732.5 626.8,-732.5 ; -373.2,-607.5 -373.2,-857.5 626.8,-857.5 626.8,-607.5 ; -248.2,-857.5 -248.2,-607.5 ; -123.2,-857.5 -123.2,-607.5 ; -63.2,-607.5 936.8,-607.5 ; 126.8,-857.5 126.8,-607.5 ; 376.8,-857.5 376.8,-607.5
  text "(TYP)" at 6318.96,705.07 h60 r90
  text "(TYP)" at 5977.27,-170.39 h60
  text ".Layer_Name" at 203.8,-1315.99 h60
M3 3D STEP Top:
  text ".Layer_Name" at 203.8,-1315.99 h60
M4 3D STEP Bottom:
  text ".Layer_Name" at 203.8,-1315.99 h60
M5 Assembly Top:
  lines w10: -665.2,-1387.67 5934.8,-1387.67 ; -665.2,-1184.33 5936.8,-1184.33 ; -665.2,-981 -665.2,-1591 3339.8,-1591 5936.8,-1591 5936.8,-981 -664.7,-981 -664.7,-1591 910.8,-1591 ; 1799.8,-1591 1799.8,-981 ; 3066.8,-1184.33 3066.8,-981 ; 3906.8,-1184.33 3906.8,-981 ; 4528.8,-1597.5 4528.8,-1394.67
  text "COMPONENTS MARKED 'DNP' SHOULD NOT BE POPULATED." at 780.3,-776 h60
  text "ASSEMBLY VARIANT:" at 779.8,-891.5 h60
  text ".VariantName" at 1815.8,-891.5 h60
  text "PCB VIEWED FROM TOP SIDE" at -601.7,-1113.17 h60
  text "BOARD #:" at 1874.8,-1113.17 h60
  text ".PRJ_Number" at 2420.3,-1113.17 h60
  text "REV:" at 3264.8,-1113.17 h60
  text ".PCB_Rev" at 3556.3,-1113.17 h60
  text "SVN REV:" at 4102.8,-1113.17 h60
  text ".VersionControl_RevNumber" at 4608.8,-1113.17 h60
  text "TID #:" at 1874.8,-1316.5 h60
  text ".TID" at 2420.3,-1316.5 h60
  text "PLOT NAME =" at -601.7,-1521.84 h60
  text ".plot_File_Name" at 203.8,-1521.84 h60
  text "GENERATED    :" at 1876.8,-1521.84 h60
  text ".Print_Date" at 2746.3,-1521.84 h60
  text ".Print_Time" at 3475.3,-1521.84 h60
  text "TEXAS INSTRUMENTS" at 4739.8,-1521.84 h60
M6 Assembly Bottom:
  lines w10: -665.7,-1184.83 5936.3,-1184.83 ; -663.7,-1388.17 5936.3,-1388.17 ; 742.3,-1598 742.3,-1395.17 ; 1364.3,-1184.83 1364.3,-981.5 ; 2204.3,-1184.83 2204.3,-981.5 ; 3471.3,-1591.5 3471.3,-981.5 ; 4360.3,-1591.5 5935.8,-1591.5 5935.8,-981.5 -665.7,-981.5 -665.7,-1591.5 1931.3,-1591.5 5936.3,-1591.5 5936.3,-981.5
  text "COMPONENTS MARKED 'DNP' SHOULD NOT BE POPULATED." at 5728.8,-775.5 h60
  text ".VariantName" at 4684.8,-891.5 h60
  text "ASSEMBLY VARIANT:" at 5723.8,-891.5 h60
  text ".VersionControl_RevNumber" at 662.3,-1113.67 h60
  text "SVN REV:" at 1168.3,-1113.67 h60
  text ".PCB_Rev" at 1714.8,-1113.67 h60
  text "REV:" at 2006.3,-1113.67 h60
  text ".PRJ_Number" at 2850.8,-1113.67 h60
  text "BOARD #:" at 3396.3,-1113.67 h60
  text "PCB VIEWED FROM BOTTOM SIDE" at 5872.8,-1113.67 h60
  text ".TID" at 2850.8,-1317 h60
  text "TID #:" at 3396.3,-1317 h60
  text "TEXAS INSTRUMENTS" at 531.3,-1522.34 h60
  text ".Print_Time" at 1795.8,-1522.34 h60
  text ".Print_Date" at 2524.8,-1522.34 h60
  text "GENERATED    :" at 3394.3,-1522.34 h60
  text ".plot_File_Name" at 5067.3,-1522.34 h60
  text "PLOT NAME =" at 5872.8,-1522.34 h60
M9 Title Sheet:
  drawing of 53 lines, arcs and shapes, not listed
  text "5" at 10357.3,7579 h70
  text "6" at 12862.3,7579 h70
  text "A" at -789.7,6436 h70
  text "A" at 14010.3,6436 h70
  text "B" at -789.7,4056 h70
  text "B" at 14010.3,4056 h70
  text "C" at -789.7,1681 h70
  text "C" at 14010.3,1681 h70
  text "PROJECT TITLE:" at 10970.3,-180 h45
  text ".PRJ_Title" at 11020.3,-313.33 h70
  text "DESIGNED FOR:" at 10970.3,-481 h45
  text ".PRJ_Customer" at 11020.3,-621 h70
  text "D" at -789.7,-689 h70
  text "D" at 14010.3,-689 h70
  text "FILE NAME:" at 10970.3,-781 h45
  text ".PCB_File_Name_No_Path" at 11020.3,-901 h70
  text "Texas Instruments (TI) and/or its licensors do not warrant the accuracy or completeness of this specification" at 6000.8,-1062.84 h45
  text "ENGINEER:" at 10970.3,-1071 h45
  text "LAYOUT BY:" at 12475.3,-1071 h45
  text "or any information contained therein. TI and/or its licensors do not warrant that this design will meet" at 5955.81,-1175.5 h45
  text ".PRJ_Engineer" at 11020.3,-1225.99 h70
  text ".PCB_Layout" at 12525.8,-1225.99 h70
  text "the specifications, will be suitable for your application or fit for any particular purpose, or will operate in" at 5955.81,-1288.17 h45
  text ".Layer_Name" at 203.8,-1315.99 h60
  text "ALTIUM DESIGNER VERSION:" at 12475.3,-1381 h45
  text "an implementation. TI and/or its licensors do not warrant that the design is production worthy. You should" at 5955.81,-1400.83 h45
  text "completely validate and test your design implementation to confirm the system functionality for your application." at 6000.8,-1513.5 h45
  text ".print_Scale" at 11020.3,-1514.33 h70
  text ".Application_BuildNumber" at 12525.8,-1514.33 h70
  text "1" at 366.63,-1721 h70
  text "2" at 2862.3,-1721 h70
  text "3" at 5351.64,-1721 h70
  text "4" at 7858.31,-1721 h70
  text "5" at 10357.3,-1721 h70
  text "6" at 12862.3,-1721 h70
M10 Fab Notes:
  drawing of 190 lines, arcs and shapes, not listed
  text "DESIGN INFORMATION" at 12007.81,5570.5 h60
  text "MIN. TRACK WIDTH:" at 11363.26,5390.5 h60
  text "6" at 12459.5,5390.5 h60
  text "MIL" at 12614.26,5390.5 h60
  text "MIN. CLEARANCE:" at 11363.26,5258.5 h60
  text "0.2" at 12399.5,5258.5 h60
  text "mm" at 12614.26,5258.5 h60
  text "MIN. VIA PAD SIZE:" at 11363.26,5126.5 h60
  text "0.5" at 12429.51,5126.5 h60
  text "mm" at 12614.26,5126.5 h60
  text "0.12mm (5MIL)" at 12058.26,4984.79 h60
  text "MINIMUM ANNULAR RING" at 11034.02,4980.5 h60
  text "EXTERNAL" at 12766.26,4980.5 h60
  text "PER" at 11234.02,4862.5 h60
  text "IPC-D-275 CLASS 2 LEVEL C" at 11454.02,4862.5 h60
  text "MIL, HOLES" at 12942.26,4750.21 h60
  text "+/-" at 12549.8,4749.5 h60
  text "+/-" at 13403.8,4749.5 h60
  text "REGISTRATION TOLERANCES:" at 11034.02,4744.5 h60
  text "METAL" at 12233.8,4744.5 h60
  text "5" at 12810,4744.5 h60
  text "3" at 13643,4744.5 h60
  text "MIL" at 13759.26,4744.5 h60
  text "+/-" at 13403.8,4631.5 h60
  text "HOLE SIZE TOLERANCE (UNLESS OTHERWISE SPECIFIED):" at 11034.02,4626.5 h60
  text "3" at 13643,4626.5 h60
  text "MIL" at 13759.26,4626.5 h60
  text "MATERIAL:" at 10959.26,4417.04 h60
  text "FR-4 High Tg" at 11945.7,4276.71 h60
  text "X" at 11232.32,4269.66 h60
  text "FR-408" at 11380.26,4268.14 h60
  text "OTHER" at 12868.26,4268.14 h60
  text "62 MIL (1.6mm) +/-10%" at 11700.36,4105.42 h60
  text "THICKNESS:" at 11034.02,4101.14 h60
  text "X" at 11572.19,4101.14 h60
  text "OTHER" at 12985.26,4101.14 h60
  text "TOLERANCE:" at 11034.02,3943.14 h60
  text "X" at 11873.33,3943.14 h60
  text "ANSI IPC-6012 TYPE 3 CLASS 2" at 12060.27,3943.14 h60
  text "OTHER +/-" at 12060.26,3787.14 h60
  text "BOW & TWIST:" at 11034.02,3630.14 h60
  text "X" at 11873.33,3630.14 h60
  text "ANSI IPC-6012 TYPE 3 CLASS 2" at 12060.27,3630.14 h60
  text "Controlled Impedance:" at 6441.79,3522.08 h60
  text "OTHER +/-" at 12060.26,3471.63 h60
  text "6.24 mil wide, 4 mil spaced differential pairs are 90 ohms +/- 10%" at 6441.78,3385.13 h60
  text "DRILLING:" at 10959.26,3333.14 h60
  text "REFERENCE:" at 11034.02,3216.14 h60
  text "X" at 11682.26,3216.14 h60
  text "AS SHOWN" at 11869.26,3216.14 h60
  text "X" at 12583.26,3216.14 h60
  text "NC_DRILL FILES" at 12720.26,3216.14 h60
  text "PTH MIN COPPER THICKNESS:" at 11034.02,3058.14 h60
  text "X" at 12384.26,3058.14 h60
  text "1MIL" at 12521.26,3058.14 h60
  text "OTHER" at 13018.26,3058.14 h60
  text "BOARD FINISH:" at 10959.26,2899.14 h60
  text "SILKSCREEN:" at 11114.48,2781.14 h60
  text "X" at 12063.26,2781.14 h60
  text "TOP" at 12189.26,2781.14 h60
  text "X" at 12573.26,2781.14 h60
  text "BOTTOM" at 12700.26,2781.14 h60
  text "SILKSCREEN COLOR:" at 11114.48,2614.14 h60
  text "X" at 12062.21,2614.14 h60
  text "WHITE" at 12189.26,2614.14 h60
  text "OTHER" at 12700.26,2614.14 h60
  text "X" at 12771.46,2460.01 h60
  text "GREEN" at 12320.26,2454.94 h60
  text "OTHER" at 12938.26,2454.94 h60
  text "RED" at 13323.75,2449.87 h60
  text "SOLDER RESIST COLOR:" at 11114.48,2444.14 h60
  text "X" at 12787.3,2289.54 h60
  text "MATTE" at 12320.26,2284.94 h60
  text "SEMI-GLOSS" at 12937.8,2284.3 h60
  text "IMMERSION GOLD (ENIG)" at 12020.25,2096.42 h60
  text "ENEPIG" at 13357.8,2093.14 h60
  text "SURFACE FINISH:" at 10959.26,2092.14 h60
  text "X" at 11833.31,2092.14 h60
  text "IMM. TIN/SILVER OR EQUIV" at 11288.8,1935.14 h60
  text "OTHER" at 12720.26,1935.14 h60
  text "ARRAY/PANEL:" at 10959.26,1756.14 h60
  text "CUT AND TRIM PER M1 BOARD OUTLINE" at 12020.26,1751.85 h60
  text "N.C. ROUTE" at 12020.26,1600.14 h60
  text "X" at 12699.26,1600.14 h60
  text "V. SCORE" at 12886.26,1600.14 h60
  text "CERTIFICATION:" at 10959.26,1463.14 h60
  text "MATERIALS AND WORKMANSHIP FOR ALL PCBS" at 11684.26,1463.14 h60
  text "TO MEET OR EXCEED THE REQUIREMENTS OF:" at 11684.26,1365.14 h60
  text "X" at 11310.76,1228.63 h60
  text "ANSI IPC-A-600F CLASS ->" at 11449.76,1228.63 h60
  text "X" at 13088.81,1228.63 h60
  text "2" at 13207.76,1228.64 h60
  text "1" at 12892.76,1227.14 h60
  text "3" at 13561.76,1227.14 h60
  text "X" at 11312.81,1069.14 h60
  text "UL 94V-0" at 11449.76,1069.14 h60
  text "X" at 12124.81,1069.14 h60
  text "RoHS" at 12261.76,1069.14 h60
  text "OTHER" at 12906.16,1069.14 h60
  text "PER ORDER" at 13303.22,1069.14 h60
  text "ADDITIONAL REQUIREMENTS:" at 10959.26,928.14 h60
  text "MICROSECTION:" at 11034.02,813.14 h60
  text "YES" at 11939.76,813.14 h60
  text "REQUIRED" at 12801.26,656.99 h60
  text "BARE BOARD ELEC. TEST:" at 11034.02,654.14 h60
  text "NONE" at 12339.76,654.14 h60
  text "PER ORDER" at 13393.26,654.14 h60
  text "X" at 13272.79,649.07 h60
  text "MANUFACTURER'S UL:" at 11034.02,497.14 h60
  text "RAIL" at 12199.76,492.85 h60
  text "METAL" at 12691.57,492.85 h60
  text "X" at 13066.8,492.5 h60
  text "SILK" at 13203.26,492.85 h60
  text ".Layer_Name" at 203.8,-1315.99 h60
M11 Gerber Information:
  lines w10: -665.2,-1387.67 5934.8,-1387.67 ; -665.2,-1184.33 5936.8,-1184.33 ; -665.2,-981 -665.2,-1591 3339.8,-1591 5936.8,-1591 5936.8,-981 -664.7,-981 -664.7,-1591 910.8,-1591 ; 1799.8,-1591 1799.8,-981 ; 3066.8,-1184.33 3066.8,-981 ; 3906.8,-1184.33 3906.8,-981 ; 4528.8,-1597.5 4528.8,-1394.67
  text "ALL ARTWORK VIEWED FROM TOP SIDE" at -601.7,-1113.17 h60
  text "BOARD #:" at 1874.8,-1113.17 h60
  text ".PRJ_Number" at 2420.3,-1113.17 h60
  text "REV:" at 3264.8,-1113.17 h60
  text ".PCB_Rev" at 3556.3,-1113.17 h60
  text "SVN REV:" at 4102.8,-1113.17 h60
  text ".VersionControl_RevNumber" at 4608.8,-1113.17 h60
  text "LAYER NAME =" at -601.7,-1315.99 h60
  text "TID #:" at 1874.8,-1316.5 h60
  text ".TID" at 2420.3,-1316.5 h60
  text "PLOT NAME =" at -601.7,-1521.84 h60
  text ".plot_File_Name" at 203.8,-1521.84 h60
  text "GENERATED    :" at 1876.8,-1521.84 h60
  text ".Print_Date" at 2746.3,-1521.84 h60
  text ".Print_Time" at 3475.3,-1521.84 h60
  text "TEXAS INSTRUMENTS" at 4739.8,-1521.84 h60
M12 Stackup:
  lines w6: 10977.44,7234.89 13837.07,7234.89 ; 10977.44,7347.49 13837.07,7347.49 ; 10917.44,6522.98 ccw(c10953.44,6522.98) 10953.44,6486.98 13861.07,6486.98 ccw(c13861.07,6522.98) 13897.07,6522.98 13897.07,7444.19 ccw(c13861.07,7444.19) 13861.07,7480.19 10953.44,7480.19 ccw(c10953.44,7444.19) 10917.44,7444.19 10917.44,6522.98
  text "Layer Stack Up Detail for: TIDA-0085-TID.PcbDoc" at 10977.44,7376.04 h51
  text "Layer" at 10977.44,7305.49 h26
  text "Gerber" at 11978.45,7305.49 h26
  text "Copper" at 12633.71,7305.49 h26
  text "Dielectric" at 13331.42,7305.49 h26
  text "Name" at 10977.44,7253.49 h26
  text "Document" at 11978.45,7253.49 h26
  text "Thickness" at 12633.71,7253.49 h26
  text "Material" at 13331.42,7253.49 h26
  text "Top Solder Mask" at 10977.44,7180.16 h36
  text "(.GTS)" at 11978.45,7180.16 h36
  text "Solder Resist" at 13331.42,7180.16 h36
  text "Top Layer" at 10977.44,7076.7 h36
  text "(.GTL)" at 11978.45,7076.7 h36
  text "1.4mil" at 12633.71,7076.7 h36
  text "FR-408" at 13331.42,7024.97 h36
  text "MidLayer1" at 10977.44,6973.24 h36
  text "(.G1)" at 11978.45,6973.24 h36
  text "1.4mil" at 12633.71,6973.24 h36
  text "FR-4" at 13331.42,6921.51 h36
  text "MidLayer2" at 10977.44,6869.78 h36
  text "(.G2)" at 11978.45,6869.78 h36
  text "1.4mil" at 12633.71,6869.78 h36
  text "FR-408" at 13331.42,6818.05 h36
  text "Bottom Layer" at 10977.44,6766.32 h36
  text "(.GBL)" at 11978.45,6766.32 h36
  text "1.4mil" at 12633.71,6766.32 h36
  text "Bottom Solder Mask" at 10977.44,6662.86 h36
  text "(.GBS)" at 11978.45,6662.86 h36
  text "Solder Resist" at 13331.42,6662.86 h36
  text ".Layer_Name" at 203.8,-1315.99 h60
M13 Component Bodies Top:
  text ".Layer_Name" at 203.8,-1315.99 h60
M14 Component Bodies Bottom:
  text ".Layer_Name" at 203.8,-1315.99 h60
M15 Courtyards Top:
  text ".Layer_Name" at 203.8,-1315.99 h60
M16 Courtyards Bottom:
  text ".Layer_Name" at 203.8,-1315.99 h60
Drill Drawing:
  text ".legend" at 701.48,4598.49 h60
  text "Drill Table" at 703.62,4457.16 h60
  text ".Layer_Name" at 203.8,-1315.99 h60

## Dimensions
5626.8,0 to 5626.8,668.5 on M2 Board Dimensions
5626.8,0 to 5936.8,668.5 on M2 Board Dimensions
-373.2,-857.5 to 626.8,-857.5 on M2 Board Dimensions
0,0 to 5936.8,668.5 on M2 Board Dimensions
0,0 to 240,4260 on M2 Board Dimensions
240,4260 to 0,4020 on M2 Board Dimensions
240,4260 to 0,4020 on M2 Board Dimensions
